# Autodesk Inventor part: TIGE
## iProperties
Shininess: 64.0
Length Units: 11269
Angle Units: 11279
Time Units: 11290
Mass Units: 11283
Length Display Precision: 3
Angle Display Precision: 2
Compacted: True
Part Number: TIGE
Document SubType Name: Modeling
Created: 2004-05
Material: Par défaut
Designer: David
Density: 0.0
Volumn: 0.0
Area: 0.0
PropertySet Name: Model Information
Control State: 0
Master: False
Checked Out: False
Author: David
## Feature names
1. Révolution1 [Revolution]
